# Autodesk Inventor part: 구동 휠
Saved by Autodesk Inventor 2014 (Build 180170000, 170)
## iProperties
Created: 2025-09
Part Number: 구동 휠
Material: 일반
Document SubType Name: Modeling
Designer: dg
Density: 1 g/cm^3
Appearance: 기본값
Author: dg
Author: jhkim
Creation Date: 2025-09-02
Sending System: Autodesk Inventor 2026
Preprocessor: ST-DEVELOPER v20.1
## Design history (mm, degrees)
node "구동 휠1"
node "솔리드1"
node "기준1"
